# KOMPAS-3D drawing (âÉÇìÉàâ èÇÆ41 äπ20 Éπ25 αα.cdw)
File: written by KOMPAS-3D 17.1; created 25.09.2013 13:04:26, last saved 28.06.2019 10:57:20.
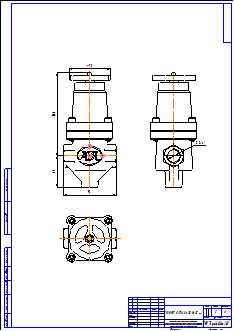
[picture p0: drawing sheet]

Sheet 1: A2, portrait

Title block, sheet 1: name: ГРАНРЕГ КАТ41 Ду20 Ру25 рр; material: Внимание! Данный продукт является объектом авторского права ООО «Торговый Дом АДЛ». / Запрещается изменение, копирование, распространение / (в том числе путем копирования на другие сайты и ресурсы в Интернете) / или любое иное использование информации и объектов без предварительного / согласия правообладателя (ООО «Торговый Дом АДЛ»).; mass: 5; sheets: 1; organisation: ООО "Торговый дом АДЛ"; sheet format: A2; stored path: \\adlc.lan\data\АДЛ_ПКД\3D-модели\ADL production\Клапаны КАТ ГРАНРЕГ\КАТ41\KOMPAS 2D\ГРАНРЕГ КАТ41 Ду20 Ру25 рр.cdw

Views: Вид 1, Проекционный вид 3
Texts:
  Klimkovich
  ADL
Dimensions and other numbers on the sheet: 75; 95; 57; 150; 1:1; 1; 5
